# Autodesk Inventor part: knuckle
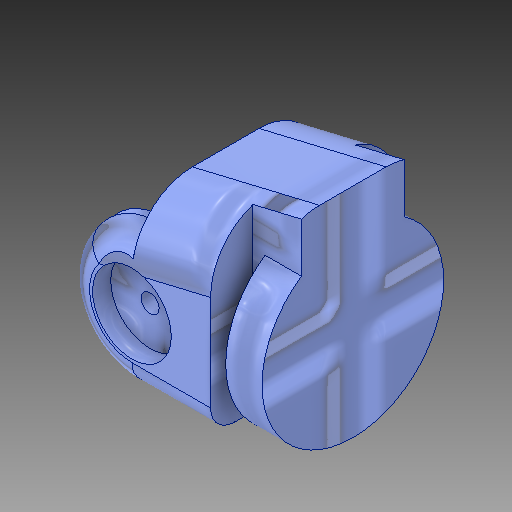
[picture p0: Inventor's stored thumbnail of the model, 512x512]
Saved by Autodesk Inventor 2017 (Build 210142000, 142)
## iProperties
Created: 2017-02
Part Number: knuckle
Material: Generic
Document SubType Name: Modeling
Designer: alez_
Density: 1 g/cm^3
Appearance: 4in Square - Light Blue
Author: alez_
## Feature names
1. Extrusion1
2. Extrusion2
3. Extrusion3
4. Extrusion4
5. Extrusion5
6. Extrusion6
7. Extrusion7
8. Extrusion8
9. Sweep1
10. Sweep2
11. Fillet1
12. Fillet2
13. Extrusion9
14. Extrusion10
15. Extrusion11
16. Extrusion12
17. Extrusion13
18. Fillet3
19. Fillet4
20. Extrusion14
## Parameters: d0 = 18 mm, d1 = 15.5 mm, d2 = 16 mm, d3 = 0, d4 = 7.75 mm, d6 = 4.25 mm, d7 = 8.5 mm, d8 = 4 mm, d9 = 0, d17 = 17 mm, d18 = 0, d19 = 13.5 mm, d20 = 17 mm, d21 = 0, d22 = 6.5 mm, d23 = 1.5 mm, d24 = 0, d25 = 1.5 mm, d26 = 0, d27 = 1.5 mm, d28 = 14 mm, d29 = 0, d30 = 5 mm, d33 = 8 mm, d34 = 0, d35 = 1.5 mm, d36 = 0, d37 = 0, d38 = 1.5 mm, d39 = 0, d40 = 0, d41 = 5 mm, d42 = 5 mm, d44 = 0, d45 = 11 mm, d47 = 0, d49 = 1 mm, d50 = 1 mm, d51 = 0.75 mm, d52 = 11 mm, d55 = 0, d56 = 10.5 mm, d57 = 1 mm, d58 = 0, d59 = 2 mm, d60 = 0, d61 = 1 mm, d62 = 2 mm, d63 = 15 mm, d64 = 3.25 mm, d65 = 0
